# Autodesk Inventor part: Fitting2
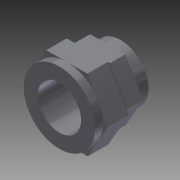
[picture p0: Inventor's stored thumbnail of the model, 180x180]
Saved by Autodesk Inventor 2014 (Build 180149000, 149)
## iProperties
Company: Autodesk, Inc.
Shininess: 64.0
Length Units: 11272
Angle Units: 11279
Time Units: 11290
Mass Units: 11286
Length Display Precision: 3
Angle Display Precision: 2
Compacted: True
Part Number: Fitting2
Document SubType Name: Modeling
Created: 2003-10
Designer: Autodesk, Inc.
Manufacturer: Standard
Standards Organization: Custom
Density: 8.03 g/cm^3
Material: Stainless Steel, Austenitic
Mass: 1632.52 g
Surface Area: 460.497 cm^2
Volume: 203.303 cm^3
Appearance: Metal-Steel (Polished)
Density: 0.0
Volumn: 0.0
Area: 0.0
PropertySet Name: Model Information
Control State: 0
Master: False
Checked Out: False
Author: Autodesk, Inc.
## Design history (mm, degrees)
sketch "Sketch1"
  geometry: C1 r 31.75 at (-12.357, 0); C2 r 34.925 at (-12.357, 0)
  constraints: 2 centre point, 1 coincident
  dimensions: "d12" = 69.85 diameter of C2; "d13" = 63.5 diameter of C1
extrude "Extrusion1" new body sketch "Sketch1" distance "d0" = 15.875; taper "d1" = 0 deg
sketch "Sketch2"
  geometry: L1 (21.767, 38.232)-(43.993, 0.266); L2 (43.993, 0.266)-(22.227, -37.967); L3 (22.227, -37.967)-(-21.767, -38.232); L4 (-21.767, -38.232)-(-43.993, -0.266); L5 (-43.993, -0.266)-(-22.227, 37.967); L6 (-22.227, 37.967)-(21.767, 38.232); C1 r 31.75 at (0, 0) reference; C2 r 34.925 at (0, 0) reference; 1 further point
  constraints: 12 end point, 1 coincident, 11 other
  dimensions: "d2" = 76.2 distance between parallel lines of L6 L3
extrude "Extrusion2" join sketch "Sketch2" distance "d3" = 19.05; taper "d4" = 0 deg
sketch "Sketch3"
  geometry: C1 r 31.75 at (0, 0) reference; C2 r 34.925 at (0, 0) reference
extrude "Extrusion3" join sketch "Sketch3" distance "d5" = 6.35; taper "d6" = 0 deg
sketch "Sketch4"
  geometry: L1 (25.394, 44.604)-(51.326, 0.31); L2 (51.326, 0.31)-(25.931, -44.294); L3 (25.931, -44.294)-(-25.394, -44.604); L4 (-25.394, -44.604)-(-51.326, -0.31); L5 (-51.326, -0.31)-(-25.931, 44.294); L6 (-25.931, 44.294)-(25.394, 44.604); L7 (22.227, -37.967)-(-21.767, -38.232) reference; C1 r 26.988 at (0, 0); C2 r 34.925 at (0, 0) reference; 1 further point
  constraints: 12 end point, 1 centre point, 1 coincident, 1 concentric, 1 parallel, 11 other
  dimensions: "d7" = 88.9 distance between parallel lines of L6 L3; "d14" = 53.975 diameter of C1
extrude "Extrusion4" join sketch "Sketch4" distance "d8" = 25.4; taper "d9" = 0 deg
sketch "Sketch5"
  geometry: L1 (-25.931, 44.294)-(25.394, 44.604) reference; C1 r 26.988 at (0, 0) reference; C2 r 44.45 at (0, 0)
  constraints: 1 centre point, 1 coincident, 1 tangent
extrude "Extrusion5" join sketch "Sketch5" distance "d10" = 9.525; taper "d11" = 0 deg
body "Solid1"
other parameters: "d15" = 0
